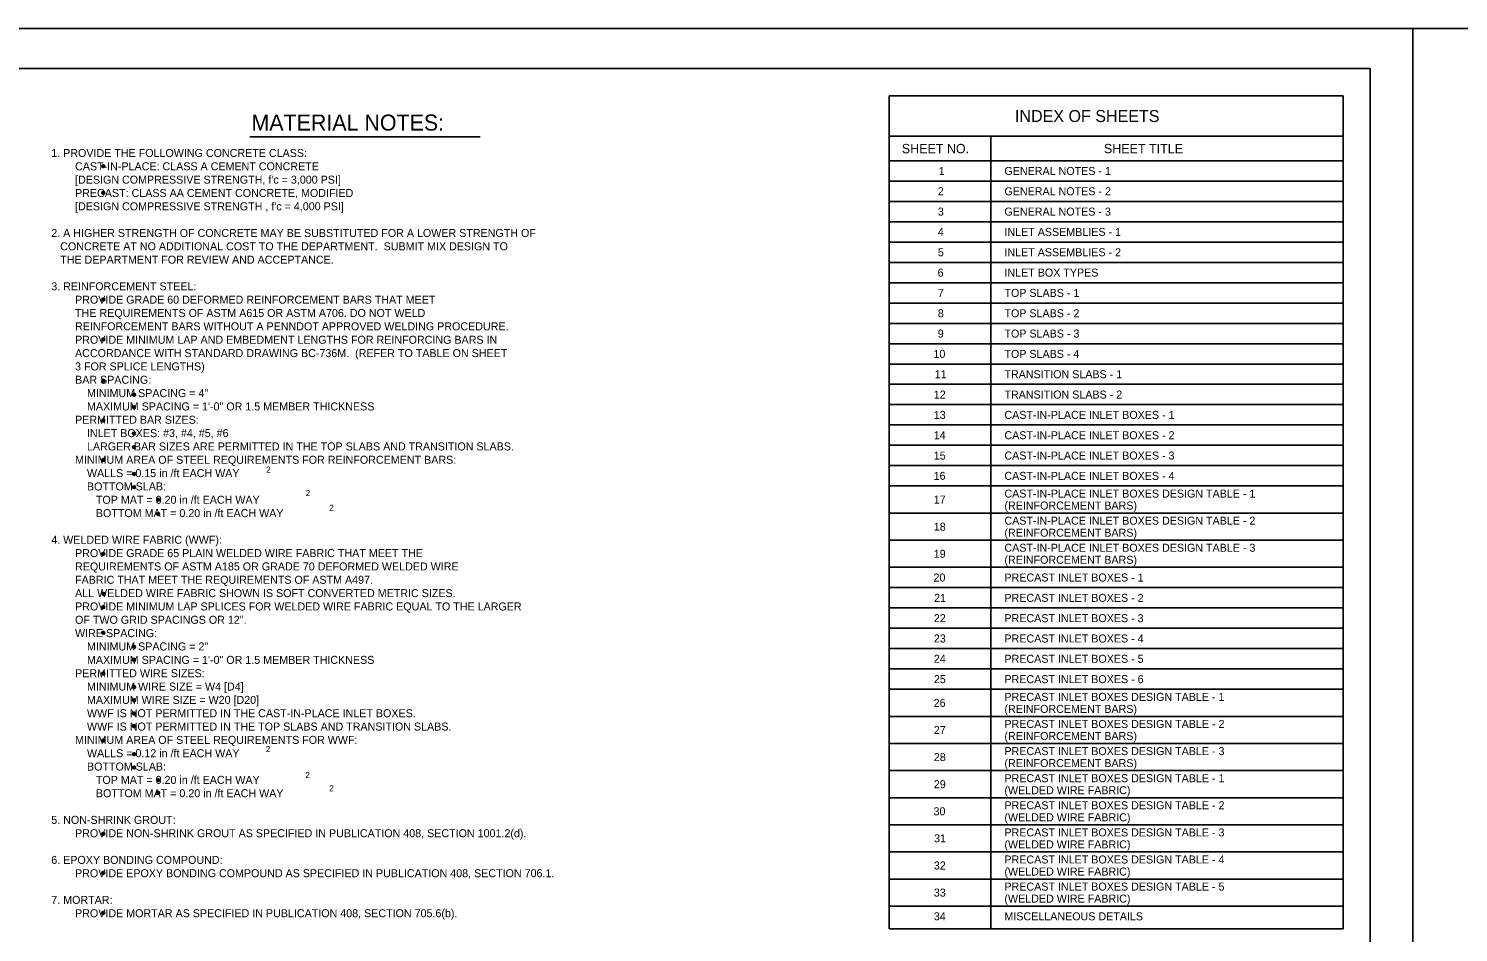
# Model space of a CAD drawing. Extents: x -6420 to 49575, y -4552 to 11624.
# Drawn here: x -5364 to -3605, y 10512 to 11624 of the extents above; entities that cross this region are included whole.
import ezdxf

# ---------------------------------------------------------------- set-up
doc = ezdxf.new("R2010")
doc.units = 0
doc.layers.add('1', color=7, linetype='Continuous')
doc.layers.add('PLT-BNDY', color=7, linetype='Continuous')

msp = doc.modelspace()

# ---------------------------------------------------------------- linework, layer by layer
at = {"layer": '1'}
for p, q in [((-4305.3, 11541.4), (-3747, 11541.4)), ((-4305.3, 10516.6), (-4305.3, 11541.4)), ((-3747, 10516.6), (-3747, 11541.4)), ((-5091.7, 11490.8), (-4808.3, 11490.8)), ((-4305.3, 11491.4), (-3747, 11491.4)), ((-4180.3, 10516.6), (-4180.3, 11491.4)), ((-4305.3, 11461.4), (-3747, 11461.4)), ((-4305.3, 11436.4), (-3747, 11436.4)), ((-4305.3, 11411.4), (-3747, 11411.4)), ((-4305.3, 11386.4), (-3747, 11386.4)), ((-4305.3, 11361.4), (-3747, 11361.4)), ((-4305.3, 11336.4), (-3747, 11336.4)), ((-4305.3, 11311.4), (-3747, 11311.4)), ((-4305.3, 11286.4), (-3747, 11286.4)), ((-4305.3, 11261.4), (-3747, 11261.4)), ((-4305.3, 11236.4), (-3747, 11236.4)), ((-4305.3, 11211.4), (-3747, 11211.4)), ((-4305.3, 11186.4), (-3747, 11186.4)), ((-4305.3, 11161.4), (-3747, 11161.4)), ((-4305.3, 11136.4), (-3747, 11136.4)), ((-4305.3, 11111.4), (-3747, 11111.4)), ((-4305.3, 11086.4), (-3747, 11086.4)), ((-4305.3, 11061.4), (-3747, 11061.4)), ((-4305.3, 11028), (-3747, 11028)), ((-4305.3, 10994.7), (-3747, 10994.7)), ((-4305.3, 10961.4), (-3747, 10961.4)), ((-4305.3, 10936.4), (-3747, 10936.4)), ((-4305.3, 10911.4), (-3747, 10911.4)), ((-4305.3, 10886.4), (-3747, 10886.4)), ((-4305.3, 10861.4), (-3747, 10861.4)), ((-4305.3, 10836.4), (-3747, 10836.4)), ((-4305.3, 10811.3), (-3747, 10811.3)), ((-4305.3, 10778), (-3747, 10778)), ((-4305.3, 10744.7), (-3747, 10744.7)), ((-4305.3, 10711.3), (-3747, 10711.3)), ((-4305.3, 10678), (-3747, 10678)), ((-4305.3, 10644.7), (-3747, 10644.7)), ((-4305.3, 10611.3), (-3747, 10611.3)), ((-4305.3, 10578), (-3747, 10578)), ((-4305.3, 10544.7), (-3747, 10544.7)), ((-4305.3, 10516.6), (-3747, 10516.6))]:
    msp.add_line(p, q, dxfattribs=at)
msp.add_lwpolyline([(-3713.7, 9724.3), (-3713.7, 11574.7), (-6292.4, 11574.7), (-6292.4, 9724.3), (-3713.7, 9724.3), (-3713.7, 9810.8), (-4369.8, 9810.8), (-4369.8, 10023), (-3713.7, 10023), (-3713.7, 10118), (-4369.8, 10118), (-4369.8, 9724.3), (-4111.3, 9724.3), (-4111.3, 9810.8), (-4111.3, 9724.3), (-3858.7, 9724.3), (-3858.7, 9810.8), (-3858.7, 9770.4), (-3713.7, 9770.4)], dxfattribs=at)
for centre, radius in [((-5272, 11454.7), 1.75), ((-5272, 11454.7), 1.31), ((-5272, 11454.7), 0.875), ((-5272, 11454.7), 0.437), ((-5272, 11421.9), 1.75), ((-5272, 11421.9), 1.31), ((-5272, 11421.9), 0.875), ((-5272, 11421.9), 0.437), ((-5272, 11290.7), 1.75), ((-5272, 11290.7), 1.31), ((-5272, 11290.7), 0.875), ((-5272, 11290.7), 0.437), ((-5272, 11241.5), 1.75), ((-5272, 11241.5), 1.31), ((-5272, 11241.5), 0.875), ((-5272, 11241.5), 0.437), ((-5272, 11190.9), 1.75), ((-5272, 11190.9), 1.31), ((-5272, 11190.9), 0.875), ((-5272, 11190.9), 0.437), ((-5234.2, 11173.6), 1.75), ((-5234.2, 11173.6), 1.31), ((-5234.2, 11173.6), 0.875), ((-5234.2, 11173.6), 0.437), ((-5234.2, 11158.3), 1.75), ((-5234.2, 11158.3), 1.31), ((-5234.2, 11158.3), 0.875), ((-5234.2, 11158.3), 0.437), ((-5272, 11141.9), 1.75), ((-5272, 11141.9), 1.31), ((-5272, 11141.9), 0.875), ((-5272, 11141.9), 0.437), ((-5234.2, 11125.9), 1.75), ((-5234.2, 11125.9), 1.31), ((-5234.2, 11125.9), 0.875), ((-5234.2, 11125.9), 0.437), ((-5234.2, 11109.1), 1.75), ((-5234.2, 11109.1), 1.31), ((-5234.2, 11109.1), 0.875), ((-5234.2, 11109.1), 0.437), ((-5272, 11093.3), 1.75), ((-5272, 11093.3), 1.31), ((-5272, 11093.3), 0.875), ((-5272, 11093.3), 0.437), ((-5234.2, 11076.2), 1.75), ((-5234.2, 11060), 1.75), ((-5234.2, 11076.2), 1.31), ((-5234.2, 11060), 1.31), ((-5234.2, 11076.2), 0.875), ((-5234.2, 11076.2), 0.437), ((-5234.2, 11060), 0.875), ((-5234.2, 11060), 0.437), ((-5204.6, 11044.5), 1.75), ((-5204.6, 11044.5), 1.31), ((-5204.6, 11044.5), 0.875), ((-5204.6, 11044.5), 0.437), ((-5204.6, 11027), 1.75), ((-5204.6, 11027), 1.31), ((-5204.6, 11027), 0.875), ((-5204.6, 11027), 0.437), ((-5272, 10978), 1.75), ((-5272, 10978), 1.31), ((-5272, 10978), 0.875), ((-5272, 10978), 0.437), ((-5271.6, 10928.6), 1.75), ((-5271.6, 10928.6), 1.31), ((-5271.6, 10928.6), 0.875), ((-5271.6, 10928.6), 0.437), ((-5272, 10912.3), 1.75), ((-5272, 10912.3), 1.31), ((-5272, 10912.3), 0.875), ((-5272, 10912.3), 0.437), ((-5272, 10880.9), 1.75), ((-5272, 10880.9), 1.31), ((-5272, 10880.9), 0.875), ((-5272, 10880.9), 0.437), ((-5234.2, 10863.4), 1.75), ((-5234.2, 10863.4), 1.31), ((-5234.2, 10863.4), 0.875), ((-5234.2, 10863.4), 0.437), ((-5234.2, 10847.7), 1.75), ((-5234.2, 10847.7), 1.31), ((-5234.2, 10847.7), 0.875), ((-5234.2, 10847.7), 0.437), ((-5272, 10830.8), 1.75), ((-5272, 10830.8), 1.31), ((-5272, 10830.8), 0.875), ((-5272, 10830.8), 0.437), ((-5234.2, 10814.1), 1.75), ((-5234.2, 10814.1), 1.31), ((-5234.2, 10797.9), 1.75), ((-5234.2, 10797.9), 1.31), ((-5234.2, 10814.1), 0.875), ((-5234.2, 10797.9), 0.875), ((-5234.2, 10814.1), 0.437), ((-5234.2, 10797.9), 0.437), ((-5234.2, 10781.6), 1.75), ((-5234.2, 10781.6), 1.31), ((-5234.2, 10781.6), 0.875), ((-5234.2, 10781.6), 0.437), ((-5234.2, 10766.1), 1.75), ((-5234.2, 10766.1), 1.31), ((-5234.2, 10766.1), 0.875), ((-5234.2, 10766.1), 0.437), ((-5272, 10748.3), 1.75), ((-5272, 10748.3), 1.31), ((-5272, 10748.3), 0.875), ((-5272, 10748.3), 0.437), ((-5234.2, 10731.5), 1.75), ((-5234.2, 10731.5), 1.31), ((-5234.2, 10731.5), 0.875), ((-5234.2, 10731.5), 0.437), ((-5234.2, 10715.2), 1.75), ((-5234.2, 10715.2), 1.31), ((-5234.2, 10715.2), 0.875), ((-5234.2, 10715.2), 0.437), ((-5204.6, 10699.6), 1.75), ((-5204.6, 10699.6), 1.31), ((-5204.6, 10699.6), 0.875), ((-5204.6, 10699.6), 0.437), ((-5204.6, 10683.8), 1.75), ((-5204.6, 10683.8), 1.31), ((-5204.6, 10683.8), 0.875), ((-5204.6, 10683.8), 0.437), ((-5272, 10633.4), 1.75), ((-5272, 10633.4), 1.31), ((-5272, 10633.4), 0.875), ((-5272, 10633.4), 0.437), ((-5272, 10585.5), 1.75), ((-5272, 10585.5), 1.31), ((-5272, 10585.5), 0.875), ((-5272, 10585.5), 0.437), ((-5272, 10536.3), 1.75), ((-5272, 10536.3), 1.31), ((-5272, 10536.3), 0.875), ((-5272, 10536.3), 0.437)]:
    msp.add_circle(centre, radius, dxfattribs=at)
at = {"layer": 'PLT-BNDY'}
for points in [[(-6420.4, 11623.9), (-3661.2, 11623.9), (-3661.2, 9675.1), (-6420.4, 9675.1)], [(-3661.2, 11623.9), (-902, 11623.9), (-902, 9675.1), (-3661.2, 9675.1)]]:
    msp.add_lwpolyline(points, close=True, dxfattribs=at)

# ---------------------------------------------------------------- texts
at = {"layer": '1'}
for s, height, p in [('MATERIAL NOTES:', 19.685, (-5089.8, 11498.5)), ('INDEX OF SHEETS', 14.764, (-4150.7, 11509)), ('1. PROVIDE THE FOLLOWING CONCRETE CLASS:', 9.843, (-5336, 11466)), ('SHEET NO.', 11.48, (-4289.9, 11470.6)), ('SHEET TITLE', 11.483, (-4041.3, 11470.6)), ('        CAST-IN-PLACE: CLASS A CEMENT CONCRETE', 9.843, (-5336, 11449.6)), ('1', 9.84, (-4244.5, 11443.9)), ('GENERAL NOTES - 1', 9.843, (-4163.7, 11443.9)), ("        [DESIGN COMPRESSIVE STRENGTH, f'c = 3,000 PSI]", 9.843, (-5336, 11433.2)), ('        PRECAST: CLASS AA CEMENT CONCRETE, MODIFIED', 9.843, (-5336, 11416.8)), ('2', 9.84, (-4245.6, 11418.9)), ('GENERAL NOTES - 2', 9.843, (-4163.7, 11418.9)), ("        [DESIGN COMPRESSIVE STRENGTH , f'c = 4,000 PSI]", 9.843, (-5336, 11400.4)), ('3', 9.84, (-4245.6, 11393.9)), ('GENERAL NOTES - 3', 9.843, (-4163.7, 11393.9)), ('4', 9.84, (-4245.6, 11368.9)), ('INLET ASSEMBLIES - 1', 9.843, (-4163.7, 11368.9)), ('2. A HIGHER STRENGTH OF CONCRETE MAY BE SUBSTITUTED FOR A LOWER STRENGTH OF', 9.843, (-5336, 11367.6)), ('   CONCRETE AT NO ADDITIONAL COST TO THE DEPARTMENT.  SUBMIT MIX DESIGN TO', 9.843, (-5336, 11351.2)), ('   THE DEPARTMENT FOR REVIEW AND ACCEPTANCE.', 9.843, (-5336, 11334.8)), ('5', 9.84, (-4245.6, 11343.9)), ('INLET ASSEMBLIES - 2', 9.843, (-4163.7, 11343.9)), ('6', 9.84, (-4245.9, 11318.9)), ('INLET BOX TYPES', 9.843, (-4163.7, 11318.9)), ('3. REINFORCEMENT STEEL:', 9.843, (-5336, 11302)), ('        PROVIDE GRADE 60 DEFORMED REINFORCEMENT BARS THAT MEET', 9.843, (-5336, 11285.6)), ('7', 9.84, (-4245.6, 11293.9)), ('TOP SLABS - 1', 9.843, (-4163.7, 11293.9)), ('        THE REQUIREMENTS OF ASTM A615 OR ASTM A706. DO NOT WELD', 9.843, (-5336, 11269.2)), ('8', 9.84, (-4245.6, 11268.9)), ('TOP SLABS - 2', 9.843, (-4163.7, 11268.9)), ('        REINFORCEMENT BARS WITHOUT A PENNDOT APPROVED WELDING PROCEDURE.', 9.843, (-5336, 11252.8)), ('        PROVIDE MINIMUM LAP AND EMBEDMENT LENGTHS FOR REINFORCING BARS IN', 9.843, (-5336, 11236.3)), ('9', 9.84, (-4245.7, 11243.9)), ('TOP SLABS - 3', 9.843, (-4163.7, 11243.9)), ('        ACCORDANCE WITH STANDARD DRAWING BC-736M.  (REFER TO TABLE ON SHEET', 9.843, (-5336, 11219.9)), ('10', 9.84, (-4251, 11218.9)), ('TOP SLABS - 4', 9.843, (-4163.7, 11218.9)), ('        3 FOR SPLICE LENGTHS)', 9.843, (-5336, 11203.5)), ('11', 9.84, (-4249.4, 11193.9)), ('TRANSITION SLABS - 1', 9.843, (-4163.7, 11193.9)), ('        BAR SPACING:', 9.843, (-5336, 11187.1)), ('            MINIMUM SPACING = 4"', 9.843, (-5336, 11170.7)), ('12', 9.84, (-4250.6, 11168.9)), ('TRANSITION SLABS - 2', 9.843, (-4163.7, 11168.9)), ('            MAXIMUM SPACING = 1\'-0" OR 1.5 MEMBER THICKNESS', 9.843, (-5336, 11154.3)), ('13', 9.84, (-4250.6, 11143.9)), ('CAST-IN-PLACE INLET BOXES - 1', 9.843, (-4163.7, 11143.9)), ('        PERMITTED BAR SIZES:', 9.843, (-5336, 11137.9)), ('            LARGER BAR SIZES ARE PERMITTED IN THE TOP SLABS AND TRANSITION SLABS.', 9.843, (-5336, 11105.1)), ('            INLET BOXES: #3, #4, #5, #6', 9.843, (-5336, 11121.5)), ('14', 9.84, (-4250.6, 11118.9)), ('CAST-IN-PLACE INLET BOXES - 2', 9.843, (-4163.7, 11118.9)), ('        MINIMUM AREA OF STEEL REQUIREMENTS FOR REINFORCEMENT BARS:', 9.843, (-5336, 11088.7)), ('15', 9.84, (-4250.6, 11093.9)), ('CAST-IN-PLACE INLET BOXES - 3', 9.843, (-4163.7, 11093.9)), ('            WALLS = 0.15 in /ft EACH WAY', 9.843, (-5336, 11072.3)), ('2', 7.5, (-5071.7, 11077.8)), ('16', 9.84, (-4250.8, 11068.9)), ('CAST-IN-PLACE INLET BOXES - 4', 9.843, (-4163.7, 11068.9)), ('            BOTTOM SLAB:', 9.843, (-5336, 11055.9)), ('               TOP MAT = 0.20 in /ft EACH WAY', 9.843, (-5336, 11039.5)), ('2', 7.5, (-5023.1, 11048.9)), ('17', 9.84, (-4250.6, 11039.8)), ('CAST-IN-PLACE INLET BOXES DESIGN TABLE - 1', 9.843, (-4163.7, 11047.1)), ('               BOTTOM MAT = 0.20 in /ft EACH WAY', 9.843, (-5336, 11023.1)), ('2', 7.5, (-4994.1, 11030.9)), ('(REINFORCEMENT BARS)', 9.843, (-4163.7, 11032.4)), ('18', 9.84, (-4250.6, 11006.4)), ('CAST-IN-PLACE INLET BOXES DESIGN TABLE - 2', 9.843, (-4163.7, 11013.8)), ('(REINFORCEMENT BARS)', 9.843, (-4163.7, 10999)), ('4. WELDED WIRE FABRIC (WWF):', 9.843, (-5336, 10990.3)), ('        PROVIDE GRADE 65 PLAIN WELDED WIRE FABRIC THAT MEET THE', 9.843, (-5336, 10973.9)), ('19', 9.84, (-4250.6, 10973.1)), ('CAST-IN-PLACE INLET BOXES DESIGN TABLE - 3', 9.843, (-4163.7, 10980.5)), ('(REINFORCEMENT BARS)', 9.843, (-4163.7, 10965.7)), ('        REQUIREMENTS OF ASTM A185 OR GRADE 70 DEFORMED WELDED WIRE', 9.843, (-5336, 10957.5)), ('        FABRIC THAT MEET THE REQUIREMENTS OF ASTM A497.', 9.843, (-5336, 10941.1)), ('20', 9.84, (-4250.9, 10943.9)), ('PRECAST INLET BOXES - 1', 9.843, (-4163.7, 10943.9)), ('        ALL WELDED WIRE FABRIC SHOWN IS SOFT CONVERTED METRIC SIZES.', 9.843, (-5336, 10924.7)), ('21', 9.84, (-4250.2, 10918.9)), ('PRECAST INLET BOXES - 2', 9.843, (-4163.7, 10918.9)), ('        PROVIDE MINIMUM LAP SPLICES FOR WELDED WIRE FABRIC EQUAL TO THE LARGER', 9.843, (-5336, 10908.3)), ('22', 9.84, (-4250.5, 10893.9)), ('PRECAST INLET BOXES - 3', 9.843, (-4163.7, 10893.9)), ('        WIRE SPACING:', 9.843, (-5336, 10875.5)), ('        OF TWO GRID SPACINGS OR 12".', 9.843, (-5336, 10891.9)), ('            MINIMUM SPACING = 2"', 9.843, (-5336, 10859.1)), ('23', 9.84, (-4250.5, 10868.9)), ('PRECAST INLET BOXES - 4', 9.843, (-4163.7, 10868.9)), ('            MAXIMUM SPACING = 1\'-0" OR 1.5 MEMBER THICKNESS', 9.843, (-5336, 10842.6)), ('24', 9.84, (-4250.5, 10843.9)), ('PRECAST INLET BOXES - 5', 9.843, (-4163.7, 10843.9)), ('        PERMITTED WIRE SIZES:', 9.843, (-5336, 10826.2)), ('            MINIMUM WIRE SIZE = W4 [D4]', 9.843, (-5336, 10809.8)), ('25', 9.84, (-4250.5, 10818.9)), ('PRECAST INLET BOXES - 6', 9.843, (-4163.7, 10818.9)), ('            MAXIMUM WIRE SIZE = W20 [D20]', 9.843, (-5336, 10793.4)), ('26', 9.84, (-4250.7, 10789.7)), ('PRECAST INLET BOXES DESIGN TABLE - 1', 9.843, (-4163.7, 10797.1)), ('            WWF IS NOT PERMITTED IN THE CAST-IN-PLACE INLET BOXES.', 9.843, (-5336, 10777)), ('(REINFORCEMENT BARS)', 9.843, (-4163.7, 10782.3)), ('            WWF IS NOT PERMITTED IN THE TOP SLABS AND TRANSITION SLABS.', 9.843, (-5336, 10760.6)), ('27', 9.84, (-4250.5, 10756.4)), ('PRECAST INLET BOXES DESIGN TABLE - 2', 9.843, (-4163.7, 10763.8)), ('        MINIMUM AREA OF STEEL REQUIREMENTS FOR WWF:', 9.843, (-5336, 10744.2)), ('(REINFORCEMENT BARS)', 9.843, (-4163.7, 10749)), ('            WALLS = 0.12 in /ft EACH WAY', 9.843, (-5336, 10727.8)), ('2', 7.5, (-5072.2, 10734.1)), ('28', 9.84, (-4250.5, 10723.1)), ('PRECAST INLET BOXES DESIGN TABLE - 3', 9.843, (-4163.7, 10730.4)), ('            BOTTOM SLAB:', 9.843, (-5336, 10711.4)), ('2', 7.5, (-5023.5, 10702.1)), ('(REINFORCEMENT BARS)', 9.843, (-4163.7, 10715.7)), ('               TOP MAT = 0.20 in /ft EACH WAY', 9.843, (-5336, 10695)), ('2', 7.5, (-4994.1, 10685.9)), ('29', 9.84, (-4250.5, 10689.7)), ('(WELDED WIRE FABRIC)', 9.843, (-4163.7, 10682.3)), ('PRECAST INLET BOXES DESIGN TABLE - 1', 9.843, (-4163.7, 10697.1)), ('               BOTTOM MAT = 0.20 in /ft EACH WAY', 9.843, (-5336, 10678.6)), ('30', 9.84, (-4250.9, 10656.4)), ('(WELDED WIRE FABRIC)', 9.843, (-4163.7, 10649)), ('PRECAST INLET BOXES DESIGN TABLE - 2', 9.843, (-4163.7, 10663.8)), ('5. NON-SHRINK GROUT:', 9.843, (-5336, 10645.8)), ('        PROVIDE NON-SHRINK GROUT AS SPECIFIED IN PUBLICATION 408, SECTION 1001.2(d).', 9.843, (-5336, 10629.4)), ('PRECAST INLET BOXES DESIGN TABLE - 3', 9.843, (-4163.7, 10630.4)), ('31', 9.84, (-4250.2, 10623.1)), ('(WELDED WIRE FABRIC)', 9.843, (-4163.7, 10615.7)), ('6. EPOXY BONDING COMPOUND:', 9.843, (-5336, 10596.6)), ('PRECAST INLET BOXES DESIGN TABLE - 4', 9.843, (-4163.7, 10597.1)), ('        PROVIDE EPOXY BONDING COMPOUND AS SPECIFIED IN PUBLICATION 408, SECTION 706.1.', 9.843, (-5336, 10580.2)), ('32', 9.84, (-4250.5, 10589.7)), ('(WELDED WIRE FABRIC)', 9.843, (-4163.7, 10582.3)), ('PRECAST INLET BOXES DESIGN TABLE - 5', 9.843, (-4163.7, 10563.8)), ('7. MORTAR:', 9.84, (-5336, 10547.4)), ('33', 9.84, (-4250.5, 10556.4)), ('(WELDED WIRE FABRIC)', 9.843, (-4163.7, 10549)), ('        PROVIDE MORTAR AS SPECIFIED IN PUBLICATION 408, SECTION 705.6(b).', 9.843, (-5336, 10531)), ('34', 9.84, (-4250.5, 10527.2)), ('MISCELLANEOUS DETAILS', 9.843, (-4163.7, 10527.2))]:
    msp.add_text(s, height=height, dxfattribs=at).set_placement(p)

doc.saveas('drawing.dxf')
